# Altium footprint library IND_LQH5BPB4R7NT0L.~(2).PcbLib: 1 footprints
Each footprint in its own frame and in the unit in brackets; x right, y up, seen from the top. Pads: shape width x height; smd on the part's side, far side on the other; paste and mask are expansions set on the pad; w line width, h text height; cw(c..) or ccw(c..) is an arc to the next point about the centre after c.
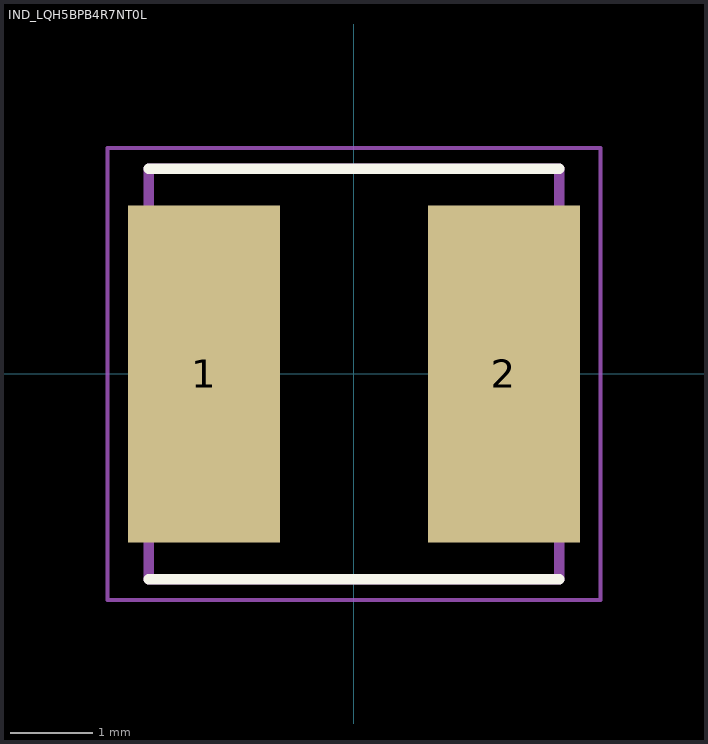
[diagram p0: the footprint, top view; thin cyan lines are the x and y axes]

## IND_LQH5BPB4R7NT0L [mm]
pads (2):
  rect 1.85x4.1 smd: 1(-1.825,0) 2(1.825,0)
Top Overlay:
  lines w0.127: -2.5,-2.5 2.5,-2.5 ; -2.5,2.5 2.5,2.5
Mechanical 13:
  lines w0.127: -2.5,-2.5 -2.5,2.5 2.5,2.5 2.5,-2.5 -2.5,-2.5
Mechanical 15:
  lines w0.05: -3,-2.75 -3,2.75 3,2.75 3,-2.75 -3,-2.75
3D body "LQH5BPN100M38L.STEP": height 4, standoff 0, extent -2.45,-2.45 2.45,2.45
